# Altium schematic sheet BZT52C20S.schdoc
size 127 x 101 mm
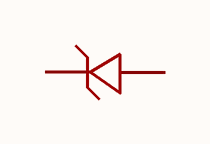
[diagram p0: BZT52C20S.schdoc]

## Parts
D?  bzt52c20s_c22618  [SOD-323_L1.8-W1.3-LS2.5-RD]  (value not drawn)

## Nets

Not connected (* = marked no-connect by the designer): D? 1(K) 2(A)

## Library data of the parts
D? = bzt52c20s_c22618: 二极管配置:1个独立式;稳压值(标称值):20V;稳压值(范围):18.8V~21.2V;耗散功率(Pd):200mW;; Manufacturer: CJ(江苏长电/长晶); AddInBom: yes; ModelId: db63db13d9e342eb939127d413d6200b; ModelTransform: 104.3305,51.181,0,0,0,0,0,-0.004,0; Diode Configuration: 1个独立式; Zener Voltage(Nom): 20V; Reverse Leakage Current (Ir): 100nA@14V; Pd - Power Dissipation: 200mW; Impedance(Zzt): 55Ω; Impedance(Zzk): 225Ω; Operating Junction Temperature Range: -55℃~+150℃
